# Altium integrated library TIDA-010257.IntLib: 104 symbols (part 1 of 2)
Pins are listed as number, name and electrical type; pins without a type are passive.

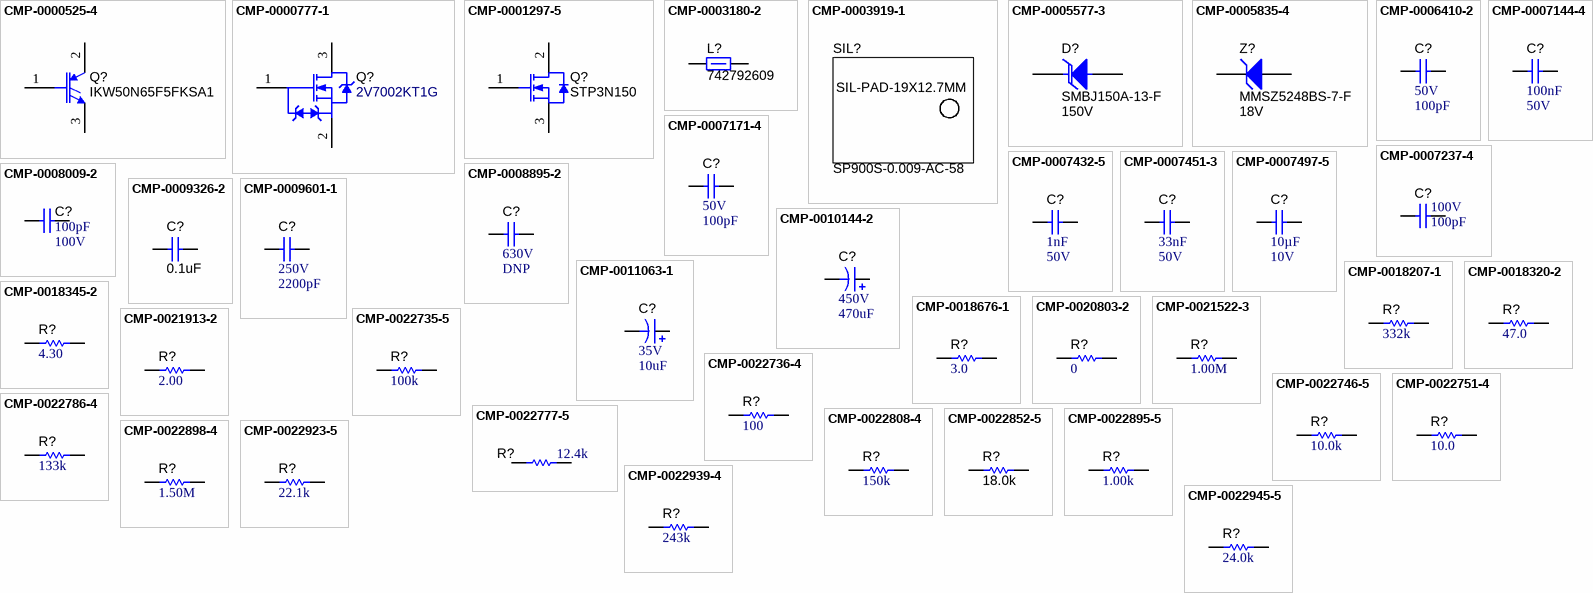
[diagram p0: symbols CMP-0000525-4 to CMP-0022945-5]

## CMP-0000525-4
designator Q?, comment IKW50N65F5FKSA1
Transistor, IGBT, 650 V, 50 A, TO-247; Manufacturer: Infineon Technologies; TaMin_C: -40°C; PNP: 0; AEC Qualified: N; TaMax_C: 175°C; SizeAreaWB_mm2: 123.2; Vceo_V: 650V; Vcesat1_V: 1.6V; Value1: 50 A; Value: 650 V; AEC Category: Q101; SizeArea_mm2: 78; SizeX_mm: 15.6; SizeY_mm: 5; SizeZ_mm: 25; IcRated_A: 50A
footprint TO-247 (Standard TO-247)
footprint TO-247_Horizontal_Down (TH, 3-Leads, Body 16.13x 21.1mm, Pitch 5.461mm)
pins: 1 G, 2 C, 3 E

## CMP-0000777-1
designator Q?, comment 2V7002KT1G
MOSFET, N-CH, 60 V, 0.32 A, AEC-Q101, SOT-23; Alternate Manufacturer: None; Manufacturer: ON Semiconductor; SizeZ_mm: 1.1; ChType: N; Value2: 0.7 nC; Value1: 2; VdsMax_V: 60V; SizeX_mm: 2.5; SizeY_mm: 3; Vgs_V: 20V; AEC Qualified: Y; Value: 60V; SizeArea_mm2: 7.5; AEC Category: Q101; IdsMax_A: 320mA; SizeAreaWB_mm2: 14; U/M: EA; QgTyp_nC: 0.7
footprint SOT-23 (SOT23, 3-Leads, Body 2.9x1.3mm, Pitch 0.95mm, Lead Span 2.5mm, IPC Medium Density)
footprint SOT-23L (SOT23, 3-Leads, Body 2.9x1.3mm, Pitch 0.95mm, Lead Span 2.5mm, IPC High Density)
footprint SOT-23M (SOT23, 3-Leads, Body 2.9x1.3mm, Pitch 0.95mm, Lead Span 2.5mm, IPC Low Density)
pins: 1 G, 2 S, 3 D

## CMP-0001297-5
designator Q?, comment STP3N150
MOSFET, N-CH, 1500 V, 2.5 A, TO-220AB; Alternate Manufacturer: None; Manufacturer: STMicroelectronics; SizeX_mm: 10.2; Vgs_V: 30V; AEC Category: Q101; ChMode: Enhancement; SizeArea_mm2: 45.9; SizeAreaWB_mm2: 79.3; VdsMax_V: 1.5kV; Value: 1500V; SizeY_mm: 4.5; Value2: 29.3 nC; IdsMax_A: 2.5A; U/M: EA; SizeZ_mm: 19.4; QgTyp_nC: 29.3; ChType: N
footprint TO-220AB (Copied from Altium's version of TO3B)
footprint TO-220AB_HORIZONTAL (For SolarMagic, with tab facing heatsink, away from PCB)
footprint TO-220AB_HORIZONTAL_SMT (For SolarMagic, with tab facing heatsink, away from PCB)
footprint TO-220AB_100mil (High Voltage staggered pins)
footprint TO-220AB_Horizontal_100mil (High Voltage staggered pins)
footprint TO-220AB_Horizontal_100mil_Standoff2300 (TH, 3-Leads, Body 10.67x9.4mm)
footprint TO-220AB_HORIZONTAL_TABUP_100mil
pins: 1 G, 2 D, 3 S
1 alternate drawing of the same symbol

## CMP-0003180-2
designator L?, comment 742792609
Ferrite Bead, 30 ohm @ 100 MHz, 3 A, 0603; Manufacturer: Wurth Elektronik; Ztyp@1GHz_Ohm: 40.472; ZTyp@100MHz_Ohm: 30; SizeAreaWB_mm2: 4.68; DCR_ohm: 40m; Value1: 0.04 ohm; Value: 30 ohm; Imax_A: 3A; SizeZ_mm: 1; SizeX_mm: 1.6; SizeY_mm: 0.8; SizeArea_mm2: 1.28
footprint 0603 (0603 from SM-752 data)
footprint 0603_HV (Ernesto recommended land pattern.  26 mil between pads.)
footprint 0603L (0603 from SM-752 data)
footprint 0603S
footprint 0603M (0603 from SM-752 data)
pins: 1, 2

## CMP-0003919-1
designator SIL?, comment SP900S-0.009-AC-58
Silcon Thermal Pad; Manufacturer: Bergquist Company
footprint SIL-PAD_19x12.7mm (Sil-Pad)

## CMP-0005577-3
designator D?, comment SMBJ150A-13-F  value 150V
Diode, TVS, Uni, 150 V, 243 Vc, SMB; Manufacturer: Diodes Inc.; Vbr_Max: 192.5V; Ipp: 2.5A; AEC Category: Q101; SizeArea_mm2: 21.336; Value1: 600W; SizeAreaWB_mm2: 44.156; Vc: 243V; SizeZ_mm: 2.6; SizeX_mm: 5.6; SizeY_mm: 3.81; Vbr_Min: 167V
footprint SMB (Molded Diode, 2-Leads, Body 5.4x3.6mm, IPC Medium Density, based on OnSemi component dimensions)
pins: 1 K, 2 A

## CMP-0005835-4
designator Z?, comment MMSZ5248BS-7-F  value 18V
Diode, Zener, 18 V, 200 mW, SOD-323; Manufacturer: Diodes Inc.; Value1: 0.2W; SizeArea_mm2: 3.645; AEC Category: Q101; Power_W: 200mW; SizeAreaWB_mm2: 8.695; SizeY_mm: 1.35; RJA_CperW: 350; SizeZ_mm: 1; SizeX_mm: 2.7
footprint SOD-323 (NXP recommended land pattern)
pins: 1 K, 2 A

## CMP-0006410-2
designator C?, comment VDC_V: 50V  ValueDisplayed: 100pF  (hidden comment: GRM1555C1H101JA01D)
CAP, CERM, 100 pF, 50 V, +/- 5%, C0G/NP0, 0402; Manufacturer: MuRata; TaMin_C: -55°C; Polarized: N; SizeAreaWB_mm2: 3; Value1: Unknown; U/M: EA; Value: 100pF; TaMax_C: 125°C; SizeZ_mm: 0.6; SizeX_mm: 1; SizeY_mm: 0.5; Cap_Case: 0402; CompType: Capacitor; AEC Category: Q200
footprint 0402 (0402 from SM-752 data)
footprint 0402S (Based on C0402S footprint from PADS legacy)
footprint 0402L (0402 from SM-752 data)
footprint 0402M (0402 from SM-752 data)
pins: 1, 2

## CMP-0007144-4
designator C?, comment Cap_F: 100nF  VDC_V: 50V  (hidden comment: GCM188R71H104KA57D)
CAP, CERM, 0.1 uF, 50 V, +/- 10%, X7R, 0603; Manufacturer: MuRata; TaMin_C: -55°C; ESR_ohm: 20m; Polarized: N; SizeAreaWB_mm2: 4.68; Value1: 0.02 ohm; U/M: EA; Value: 0.1uF; TaMax_C: 125°C; SizeZ_mm: 1; SizeX_mm: 1.6; SizeY_mm: 0.8; Cap_Case: 0603; SizeArea_mm2: 1.28; CompType: Capacitor; IRMS_A: 1.84A; AEC Category: Q200
footprint 0603 (0603 from SM-752 data)
footprint 0603_HV (Ernesto recommended land pattern.  26 mil between pads.)
footprint 0603L (0603 from SM-752 data)
footprint 0603S
footprint 0603M (0603 from SM-752 data)
pins: 1, 2

## CMP-0007171-4
designator C?, comment VDC_V: 50V  ValueDisplayed: 100pF  (hidden comment: GRM1885C1H101JA01D)
CAP, CERM, 100 pF, 50 V, +/- 5%, C0G/NP0, 0603; Manufacturer: MuRata; TaMin_C: -55°C; Polarized: N; SizeAreaWB_mm2: 4.68; Value1: Unknown; U/M: EA; Value: 100pF; TaMax_C: 125°C; SizeZ_mm: 1; SizeX_mm: 1.6; SizeY_mm: 0.8; Cap_Case: 0603; SizeArea_mm2: 1.28; CompType: Capacitor; AEC Category: Q200
footprint 0603 (0603 from SM-752 data)
footprint 0603_HV (Ernesto recommended land pattern.  26 mil between pads.)
footprint 0603L (0603 from SM-752 data)
footprint 0603S
footprint 0603M (0603 from SM-752 data)
pins: 1, 2

## CMP-0007237-4
designator C?, comment VDC_V: 100V  ValueDisplayed: 100pF  (hidden comment: GRM1885C2A101JA01D)
CAP, CERM, 100 pF, 100 V, +/- 5%, C0G/NP0, 0603; Manufacturer: MuRata; TaMin_C: -55°C; Polarized: N; SizeAreaWB_mm2: 4.68; Value1: Unknown; U/M: EA; Value: 100pF; TaMax_C: 125°C; SizeZ_mm: 1; SizeX_mm: 1.6; SizeY_mm: 0.8; Cap_Case: 0603; SizeArea_mm2: 1.28; CompType: Capacitor; AEC Category: Q200
footprint 0603 (0603 from SM-752 data)
footprint 0603_HV (Ernesto recommended land pattern.  26 mil between pads.)
footprint 0603L (0603 from SM-752 data)
footprint 0603S
footprint 0603M (0603 from SM-752 data)
pins: 1, 2

## CMP-0007432-5
designator C?, comment Cap_F: 1nF  VDC_V: 50V  (hidden comment: GRM188R71H102KA01D)
CAP, CERM, 1000 pF, 50 V, +/- 10%, X7R, 0603; Manufacturer: MuRata; TaMin_C: -55°C; Polarized: N; SizeAreaWB_mm2: 4.68; Value1: Unknown; U/M: EA; Value: 1000pF; TaMax_C: 125°C; SizeZ_mm: 1; SizeX_mm: 1.6; SizeY_mm: 0.8; Cap_Case: 0603; SizeArea_mm2: 1.28; CompType: Capacitor; AEC Category: Q200
footprint 0603 (0603 from SM-752 data)
footprint 0603_HV (Ernesto recommended land pattern.  26 mil between pads.)
footprint 0603L (0603 from SM-752 data)
footprint 0603S
footprint 0603M (0603 from SM-752 data)
pins: 1, 2

## CMP-0007451-3
designator C?, comment Cap_F: 33nF  VDC_V: 50V  (hidden comment: GRM188R71H333KA61D)
CAP, CERM, 0.033 uF, 50 V, +/- 10%, X7R, 0603; Manufacturer: MuRata; TaMin_C: -55°C; Polarized: N; SizeAreaWB_mm2: 4.68; Value1: Unknown; U/M: EA; TaMax_C: 125°C; SizeZ_mm: 1; SizeX_mm: 1.6; SizeY_mm: 0.8; Cap_Case: 0603; SizeArea_mm2: 1.28; CompType: Capacitor; AEC Category: Q200
footprint 0603 (0603 from SM-752 data)
footprint 0603_HV (Ernesto recommended land pattern.  26 mil between pads.)
footprint 0603L (0603 from SM-752 data)
footprint 0603S
footprint 0603M (0603 from SM-752 data)
pins: 1, 2

## CMP-0007497-5
designator C?, comment Cap_F: 10µF  VDC_V: 10V  (hidden comment: GRM188Z71A106MA73D)
CAP, CERM, 10 uF, 10 V, +/- 20%, X7R, 0603; Manufacturer: MuRata; TaMin_C: -55°C; Polarized: N; SizeAreaWB_mm2: 4.68; Value1: Unknown; U/M: EA; Value: 10uF; TaMax_C: 125°C; SizeZ_mm: 1; SizeX_mm: 1.6; SizeY_mm: 0.8; Cap_Case: 0603; SizeArea_mm2: 1.28; CompType: Capacitor; AEC Category: Q200
footprint 0603 (0603 from SM-752 data)
footprint 0603_HV (Ernesto recommended land pattern.  26 mil between pads.)
footprint 0603L (0603 from SM-752 data)
footprint 0603S
footprint 0603M (0603 from SM-752 data)
pins: 1, 2

## CMP-0008009-2
designator C?, comment VDC_V: 100V  ValueDisplayed: 100pF  (hidden comment: GCM2165C2A101JA16D)
CAP, CERM, 100 pF, 100 V, +/- 5%, C0G/NP0, AEC-Q200 Grade 1, 0805; Manufacturer: MuRata; TaMin_C: -55°C; Polarized: N; SizeAreaWB_mm2: 6.75; Value1: Unknown; U/M: EA; Value: 100pF; TaMax_C: 105°C; SizeZ_mm: 1.45; SizeX_mm: 2; SizeY_mm: 1.25; Cap_Case: 0805; SizeArea_mm2: 2.5; CompType: Capacitor; AEC Qualified: Y; AEC Grade: 1; AEC Category: Q200
footprint 0805_HV (0805 with 30mil clearance between pads)
footprint 0805M (0805 from SM-752 data)
footprint 0805 (0805 from SM-752 data)
footprint 0805L (0805 from SM-752 data)
footprint 0805_HV1 (Custom footprint based on analyzing multiple manufacturer recommendations)
pins: 1, 2

## CMP-0008895-2
designator C?, comment VDC_V: 630V  (hidden comment: DNP)
Manufacturer: MuRata; Manufacturer Part Number: GRM31A7U2J471JW31D; TaMin_C: -55°C; Polarized: N; TempCo: U2J; SizeAreaWB_mm2: 10.92; Value1: Unknown; U/M: EA; TaMax_C: 125°C; Tolerance_%: 5%; SizeZ_mm: 1.35; SizeX_mm: 3.2; SizeY_mm: 1.6; Cap_Case: 1206; SizeArea_mm2: 5.12; CompType: Capacitor; AEC Category: Q200
footprint 1206 (1206 from SM-752 data)
footprint 1206L (1206 from SM-752 data)
footprint 1206M (1206 from SM-752 data)
pins: 1, 2

## CMP-0009326-2
designator C?, comment ValueDisplayed: 0.1uF  (hidden comment: C1812W104KDRACTU)
CAP, CERM, 0.1 uF, 1000 V, +/- 10%, X7R, 1812; Manufacturer: Kemet; Polarized: N; CompType: Capacitor; Value: 0.1uF; U/M: EA; Cap_F: 100nF; Value1: Unknown; VDC_V: 1kV; Value2: 1000V; TaMin_C: -55°C; TaMax_C: 125°C; Cap_Case: 1812; AEC Category: Q200; SizeArea_mm2: 14.4; SizeAreaWB_mm2: 23.1; SizeX_mm: 4.5; SizeY_mm: 3.2; SizeZ_mm: 2.54
footprint 1812_254 (SMD, 2-Leads, Body 4.8x3.4mm)
pins: 1, 2

## CMP-0009601-1
designator C?, comment VDC_V: 250V  ValueDisplayed: 2200pF  (hidden comment: DE1E3KX222MA4BL01)
CAP, CERM, 2200 pF, 250 V, +/- 20%, E, Cap, 7x12x9 mm; Manufacturer: MuRata; TaMin_C: -25°C; Polarized: N; SizeAreaWB_mm2: 121.5; Value1: Unknown; U/M: EA; Value: 2200pF; TaMax_C: 85°C; SizeZ_mm: 12.5; SizeX_mm: 11.5; SizeY_mm: 7; Cap_Case: CAPRD1000W60D900H1200; SizeArea_mm2: 80.5; CompType: Capacitor; Cap_F: 2.2nF; AEC Category: Q200
footprint CAPRD1000W60D900H1200 (Disk, Radial Capacitor)
pins: 1, 2

## CMP-0010144-2
designator C?, comment VDC_V: 450V  ValueDisplayed: 470uF  (hidden comment: MAL215757471E3)
CAP, AL, 470 uF, 450 V, +/- 20%, 0.42 ohm, TH; Manufacturer: Vishay-Bccomponents; Manufacturer: Vishay/Bccomponents; TaMin_C: -25°C; ESR_ohm: 0.42; Polarized: Y; SizeAreaWB_mm2: 1369; U/M: EA; Value: 470uF; TaMax_C: 85°C; SizeZ_mm: 52; SizeX_mm: 35; Cap_Case: 35x50mm; SizeArea_mm2: 1225; CompType: Capacitor; AEC Qualified: N; Cap_F: 470µF; IRMS_A: 2.6A; AEC Category: Q200
footprint 157PUM-SI_3500x5000 (TH, 2-Leads, Dia 35mm, Pin Spacing 10mm)
pins: 1 +, 2 -

## CMP-0011063-1
designator C?, comment VDC_V: 35V  ValueDisplayed: 10uF  (hidden comment: EMZA350ADA100ME61G)
CAP, AL, 10 uF, 35 V, +/- 20%, 0.7 ohm, SMD; Manufacturer: Chemi-Con; TaMin_C: -55°C; ESR_ohm: 0.7; Polarized: Y; SizeAreaWB_mm2: 53.29; Value1: 0.7 ohm; U/M: EA; Value: 10uF; TaMax_C: 105°C; SizeZ_mm: 5.8; SizeX_mm: 5.3; Cap_Case: E61; SizeArea_mm2: 28.09; CompType: Capacitor; Cap_F: 10µF; IRMS_A: 160mA; AEC Category: Q200
footprint CAPSMT_62_E61 (5 x 5.8mm:  Chemi-Con E61)
pins: 1 +, 2 -

## CMP-0018207-1
designator R?, comment ValueDisplayed: 332k  (hidden comment: RC1206FR-07332KL)
RES, 332 k, 1%, 0.25 W, 1206; Manufacturer: Yageo America; Power_W: 250mW; TempCo: 100 ppm/C; U/M: EA; Value: 332k; EIA_Code: E96; SizeX_mm: 3.2; SizeY_mm: 1.6; SizeZ_mm: 1.35; Value2: 0.25W; SizeArea_mm2: 5.12; CompType: Resistor; VDC_V: 200V; AEC Category: Q200
footprint 1206 (1206 from SM-752 data)
footprint 1206L (1206 from SM-752 data)
footprint 1206M (1206 from SM-752 data)
pins: 1, 2

## CMP-0018320-2
designator R?, comment ValueDisplayed: 47.0  (hidden comment: RC1206FR-0747RL)
RES, 47.0, 1%, 0.25 W, 1206; Manufacturer: Yageo America; Power_W: 250mW; TempCo: 100 ppm/C; Value_Code: 47R0; U/M: EA; Value: 47.0; Res_ohm: 47; SizeX_mm: 3.2; SizeY_mm: 1.6; SizeZ_mm: 1.35; Value2: 0.25W; SizeArea_mm2: 5.12; CompType: Resistor; VDC_V: 200V; AEC Category: Q200
footprint 1206 (1206 from SM-752 data)
footprint 1206L (1206 from SM-752 data)
footprint 1206M (1206 from SM-752 data)
pins: 1, 2

## CMP-0018345-2
designator R?, comment ValueDisplayed: 4.30  (hidden comment: RC1206FR-074R3L)
RES, 4.30, 1%, 0.25 W, 1206; Manufacturer: Yageo America; Power_W: 250mW; TempCo: 200 ppm/C; Value_Code: 4R30; U/M: EA; Value: 4.30; Res_ohm: 4.3; SizeX_mm: 3.2; SizeY_mm: 1.6; SizeZ_mm: 1.35; Value2: 0.25W; SizeArea_mm2: 5.12; CompType: Resistor; VDC_V: 200V; AEC Category: Q200
footprint 1206 (1206 from SM-752 data)
footprint 1206L (1206 from SM-752 data)
footprint 1206M (1206 from SM-752 data)
pins: 1, 2

## CMP-0018676-1
designator R?, comment ValueDisplayed: 3.0  (hidden comment: CRCW12063R00JNEA)
RES, 3.0, 5%, 0.25 W, 1206; Manufacturer: Vishay-Dale; Manufacturer: Vishay/Dale; Power_W: 250mW; TempCo: 200 ppm/C; Value_Code: 3R00; U/M: EA; Value: 3.0; EIA_Code: E24; Res_ohm: 3; SizeX_mm: 3.2; SizeY_mm: 1.6; SizeZ_mm: 1.35; Value2: 0.25W; SizeArea_mm2: 5.12; CompType: Resistor; VDC_V: 200V; AEC Category: Q200
footprint 1206 (1206 from SM-752 data)
footprint 1206L (1206 from SM-752 data)
footprint 1206M (1206 from SM-752 data)
pins: 1, 2

## CMP-0020803-2
designator R?, comment ValueDisplayed: 0  (hidden comment: RC0805JR-070RL)
RES, 0, 5%, 0.125 W, 0805; Manufacturer: Yageo America; Power_W: 125mW; TempCo: 200 ppm/C; Value_Code: 0000; U/M: EA; Value: 0; EIA_Code: E24; SizeX_mm: 2; SizeY_mm: 1.25; SizeZ_mm: 1.45; Value2: 0.125W; SizeArea_mm2: 2.5; CompType: Resistor; VDC_V: 150V; AEC Category: Q200
footprint 0805_HV (0805 with 30mil clearance between pads)
footprint 0805M (0805 from SM-752 data)
footprint 0805 (0805 from SM-752 data)
footprint 0805L (0805 from SM-752 data)
footprint 0805_HV1 (Custom footprint based on analyzing multiple manufacturer recommendations)
pins: 1, 2

## CMP-0021522-3
designator R?, comment ValueDisplayed: 1.00M  (hidden comment: ERJ-6ENF1004V)
RES, 1.00 M, 1%, 0.125 W, AEC-Q200 Grade 0, 0805; Manufacturer: Panasonic; Power_W: 125mW; TempCo: 100 ppm/C; Value_Code: 1M00; Value: 1.00Meg; EIA_Code: E96; Res_ohm: 1M; SizeX_mm: 2; SizeY_mm: 1.25; SizeZ_mm: 1.45; Value2: 0.125W; SizeArea_mm2: 2.5; CompType: Resistor; AEC Qualified: Y; AEC Category: Q200; AEC Grade: 0; SizeAreaWB_mm2: 6.75
footprint 0805_HV (0805 with 30mil clearance between pads)
footprint 0805_HV1 (Custom footprint based on analyzing multiple manufacturer recommendations)
footprint 0805 (0805 from SM-752 data)
footprint 0805M (0805 from SM-752 data)
footprint 0805L (0805 from SM-752 data)
pins: 1, 2

## CMP-0021913-2
designator R?, comment ValueDisplayed: 2.00  (hidden comment: RC0805FR-072RL)
RES, 2.00, 1%, 0.125 W, 0805; Manufacturer: Yageo America; Power_W: 125mW; TempCo: 200 ppm/C; Value_Code: 2R00; U/M: EA; Value: 2.00; EIA_Code: E96; Res_ohm: 2; SizeY_mm: 1.25; SizeZ_mm: 1.45; Value2: 0.125W; SizeArea_mm2: 2.5; CompType: Resistor; VDC_V: 150V; AEC Category: Q200
footprint 0805_HV (0805 with 30mil clearance between pads)
footprint 0805M (0805 from SM-752 data)
footprint 0805 (0805 from SM-752 data)
footprint 0805L (0805 from SM-752 data)
footprint 0805_HV1 (Custom footprint based on analyzing multiple manufacturer recommendations)
pins: 1, 2

## CMP-0022735-5
designator R?, comment ValueDisplayed: 100k  (hidden comment: RC0603FR-07100KL)
RES, 100 k, 1%, 0.1 W, 0603; Manufacturer: Yageo; Power_W: 100mW; TempCo: 100 ppm/C; Value: 100k; EIA_Code: E96; SizeX_mm: 1.6; SizeY_mm: 0.8; SizeZ_mm: 1; Value2: 0.1W; SizeArea_mm2: 1.28; CompType: Resistor; AEC Qualified: N; VDC_V: 75V; AEC Category: Q200; SizeAreaWB_mm2: 4.68
footprint 0603 (0603 from SM-752 data)
footprint 0603_HV (Ernesto recommended land pattern.  26 mil between pads.)
footprint 0603L (0603 from SM-752 data)
footprint 0603S
footprint 0603M (0603 from SM-752 data)
pins: 1, 2

## CMP-0022736-4
designator R?, comment ValueDisplayed: 100  (hidden comment: RC0603FR-07100RL)
RES, 100, 1%, 0.1 W, 0603; Manufacturer: Yageo; Power_W: 100mW; TempCo: 100 ppm/C; Value_Code: 100R; Value: 100; EIA_Code: E96; SizeX_mm: 1.6; SizeY_mm: 0.8; SizeZ_mm: 1; Value2: 0.1W; SizeArea_mm2: 1.28; CompType: Resistor; AEC Qualified: N; VDC_V: 75V; AEC Category: Q200; SizeAreaWB_mm2: 4.68
footprint 0603 (0603 from SM-752 data)
footprint 0603_HV (Ernesto recommended land pattern.  26 mil between pads.)
footprint 0603L (0603 from SM-752 data)
footprint 0603S
footprint 0603M (0603 from SM-752 data)
pins: 1, 2

## CMP-0022746-5
designator R?, comment ValueDisplayed: 10.0k  (hidden comment: RC0603FR-0710KL)
RES, 10.0 k, 1%, 0.1 W, 0603; Manufacturer: Yageo; Power_W: 100mW; TempCo: 100 ppm/C; Value_Code: 10k0; Value: 10.0k; EIA_Code: E96; Res_ohm: 10k; SizeX_mm: 1.6; SizeY_mm: 0.8; SizeZ_mm: 1; Value2: 0.1W; SizeArea_mm2: 1.28; CompType: Resistor; AEC Qualified: N; VDC_V: 75V; AEC Category: Q200; SizeAreaWB_mm2: 4.68
footprint 0603 (0603 from SM-752 data)
footprint 0603_HV (Ernesto recommended land pattern.  26 mil between pads.)
footprint 0603L (0603 from SM-752 data)
footprint 0603S
footprint 0603M (0603 from SM-752 data)
pins: 1, 2

## CMP-0022751-4
designator R?, comment ValueDisplayed: 10.0  (hidden comment: RC0603FR-0710RL)
RES, 10.0, 1%, 0.1 W, 0603; Manufacturer: Yageo; Power_W: 100mW; TempCo: 100 ppm/C; Value_Code: 10R0; Value: 10.0; EIA_Code: E96; Res_ohm: 10; SizeX_mm: 1.6; SizeY_mm: 0.8; SizeZ_mm: 1; Value2: 0.1W; SizeArea_mm2: 1.28; CompType: Resistor; AEC Qualified: N; VDC_V: 75V; AEC Category: Q200; SizeAreaWB_mm2: 4.68
footprint 0603 (0603 from SM-752 data)
footprint 0603_HV (Ernesto recommended land pattern.  26 mil between pads.)
footprint 0603L (0603 from SM-752 data)
footprint 0603S
footprint 0603M (0603 from SM-752 data)
pins: 1, 2

## CMP-0022777-5
designator R?, comment ValueDisplayed: 12.4k  (hidden comment: RC0603FR-0712K4L)
RES, 12.4 k, 1%, 0.1 W, 0603; Manufacturer: Yageo; Power_W: 100mW; TempCo: 100 ppm/C; Value_Code: 12k4; Value: 12.4k; EIA_Code: E96; SizeX_mm: 1.6; SizeY_mm: 0.8; SizeZ_mm: 1; Value2: 0.1W; SizeArea_mm2: 1.28; CompType: Resistor; AEC Qualified: N; VDC_V: 75V; AEC Category: Q200; SizeAreaWB_mm2: 4.68
footprint 0603 (0603 from SM-752 data)
footprint 0603_HV (Ernesto recommended land pattern.  26 mil between pads.)
footprint 0603L (0603 from SM-752 data)
footprint 0603S
footprint 0603M (0603 from SM-752 data)
pins: 1, 2

## CMP-0022786-4
designator R?, comment ValueDisplayed: 133k  (hidden comment: RC0603FR-07133KL)
RES, 133 k, 1%, 0.1 W, 0603; Manufacturer: Yageo; Power_W: 100mW; TempCo: 100 ppm/C; Value: 133k; EIA_Code: E96; SizeX_mm: 1.6; SizeY_mm: 0.8; SizeZ_mm: 1; Value2: 0.1W; SizeArea_mm2: 1.28; CompType: Resistor; AEC Qualified: N; VDC_V: 75V; AEC Category: Q200; SizeAreaWB_mm2: 4.68
footprint 0603 (0603 from SM-752 data)
footprint 0603_HV (Ernesto recommended land pattern.  26 mil between pads.)
footprint 0603L (0603 from SM-752 data)
footprint 0603S
footprint 0603M (0603 from SM-752 data)
pins: 1, 2

## CMP-0022808-4
designator R?, comment ValueDisplayed: 150k  (hidden comment: RC0603FR-07150KL)
RES, 150 k, 1%, 0.1 W, 0603; Manufacturer: Yageo; Power_W: 100mW; TempCo: 100 ppm/C; Value: 150k; EIA_Code: E96; SizeX_mm: 1.6; SizeY_mm: 0.8; SizeZ_mm: 1; Value2: 0.1W; SizeArea_mm2: 1.28; CompType: Resistor; AEC Qualified: N; VDC_V: 75V; AEC Category: Q200; SizeAreaWB_mm2: 4.68
footprint 0603 (0603 from SM-752 data)
footprint 0603_HV (Ernesto recommended land pattern.  26 mil between pads.)
footprint 0603L (0603 from SM-752 data)
footprint 0603S
footprint 0603M (0603 from SM-752 data)
pins: 1, 2

## CMP-0022852-5
designator R?, comment ValueDisplayed: 18.0k  (hidden comment: RC0603FR-0718KL)
RES, 18.0 k, 1%, 0.1 W, 0603; Manufacturer: Yageo; Power_W: 100mW; TempCo: 100 ppm/C; Value_Code: 18k0; Value: 18.0k; Res_ohm: 18k; SizeX_mm: 1.6; SizeY_mm: 0.8; SizeZ_mm: 1; Value2: 0.1W; SizeArea_mm2: 1.28; CompType: Resistor; AEC Qualified: N; VDC_V: 75V; AEC Category: Q200; SizeAreaWB_mm2: 4.68
footprint 0603 (0603 from SM-752 data)
footprint 0603_HV (Ernesto recommended land pattern.  26 mil between pads.)
footprint 0603L (0603 from SM-752 data)
footprint 0603S
footprint 0603M (0603 from SM-752 data)
pins: 1, 2

## CMP-0022895-5
designator R?, comment ValueDisplayed: 1.00k  (hidden comment: RC0603FR-071KL)
RES, 1.00 k, 1%, 0.1 W, 0603; Manufacturer: Yageo; Power_W: 100mW; TempCo: 100 ppm/C; Value_Code: 1k00; Value: 1.00k; EIA_Code: E96; Res_ohm: 1k; SizeX_mm: 1.6; SizeY_mm: 0.8; SizeZ_mm: 1; Value2: 0.1W; SizeArea_mm2: 1.28; CompType: Resistor; AEC Qualified: N; VDC_V: 75V; AEC Category: Q200; SizeAreaWB_mm2: 4.68
footprint 0603 (0603 from SM-752 data)
footprint 0603_HV (Ernesto recommended land pattern.  26 mil between pads.)
footprint 0603L (0603 from SM-752 data)
footprint 0603S
footprint 0603M (0603 from SM-752 data)
pins: 1, 2

## CMP-0022898-4
designator R?, comment ValueDisplayed: 1.50M  (hidden comment: RC0603FR-071M5L)
RES, 1.50 M, 1%, 0.1 W, 0603; Manufacturer: Yageo; Power_W: 100mW; TempCo: 100 ppm/C; Value_Code: 1M50; Value: 1.50Meg; EIA_Code: E96; Res_ohm: 1.5M; SizeX_mm: 1.6; SizeY_mm: 0.8; SizeZ_mm: 1; Value2: 0.1W; SizeArea_mm2: 1.28; CompType: Resistor; AEC Qualified: N; VDC_V: 75V; AEC Category: Q200; SizeAreaWB_mm2: 4.68
footprint 0603 (0603 from SM-752 data)
footprint 0603_HV (Ernesto recommended land pattern.  26 mil between pads.)
footprint 0603L (0603 from SM-752 data)
footprint 0603S
footprint 0603M (0603 from SM-752 data)
pins: 1, 2

## CMP-0022923-5
designator R?, comment ValueDisplayed: 22.1k  (hidden comment: RC0603FR-0722K1L)
RES, 22.1 k, 1%, 0.1 W, 0603; Manufacturer: Yageo; Power_W: 100mW; TempCo: 100 ppm/C; Value_Code: 22k1; Value: 22.1k; EIA_Code: E96; SizeX_mm: 1.6; SizeY_mm: 0.8; SizeZ_mm: 1; Value2: 0.1W; SizeArea_mm2: 1.28; CompType: Resistor; AEC Qualified: N; VDC_V: 75V; AEC Category: Q200; SizeAreaWB_mm2: 4.68
footprint 0603 (0603 from SM-752 data)
footprint 0603_HV (Ernesto recommended land pattern.  26 mil between pads.)
footprint 0603L (0603 from SM-752 data)
footprint 0603S
footprint 0603M (0603 from SM-752 data)
pins: 1, 2

## CMP-0022939-4
designator R?, comment ValueDisplayed: 243k  (hidden comment: RC0603FR-07243KL)
RES, 243 k, 1%, 0.1 W, 0603; Manufacturer: Yageo; Power_W: 100mW; TempCo: 100 ppm/C; Value: 243k; EIA_Code: E96; SizeX_mm: 1.6; SizeY_mm: 0.8; SizeZ_mm: 1; Value2: 0.1W; SizeArea_mm2: 1.28; CompType: Resistor; AEC Qualified: N; VDC_V: 75V; AEC Category: Q200; SizeAreaWB_mm2: 4.68
footprint 0603 (0603 from SM-752 data)
footprint 0603_HV (Ernesto recommended land pattern.  26 mil between pads.)
footprint 0603L (0603 from SM-752 data)
footprint 0603S
footprint 0603M (0603 from SM-752 data)
pins: 1, 2

## CMP-0022945-5
designator R?, comment ValueDisplayed: 24.0k  (hidden comment: RC0603FR-0724KL)
RES, 24.0 k, 1%, 0.1 W, 0603; Manufacturer: Yageo; Power_W: 100mW; TempCo: 100 ppm/C; Value_Code: 24k0; Value: 24.0k; Res_ohm: 24k; SizeX_mm: 1.6; SizeY_mm: 0.8; SizeZ_mm: 1; Value2: 0.1W; SizeArea_mm2: 1.28; CompType: Resistor; AEC Qualified: N; VDC_V: 75V; AEC Category: Q200; SizeAreaWB_mm2: 4.68
footprint 0603 (0603 from SM-752 data)
footprint 0603_HV (Ernesto recommended land pattern.  26 mil between pads.)
footprint 0603L (0603 from SM-752 data)
footprint 0603S
footprint 0603M (0603 from SM-752 data)
pins: 1, 2

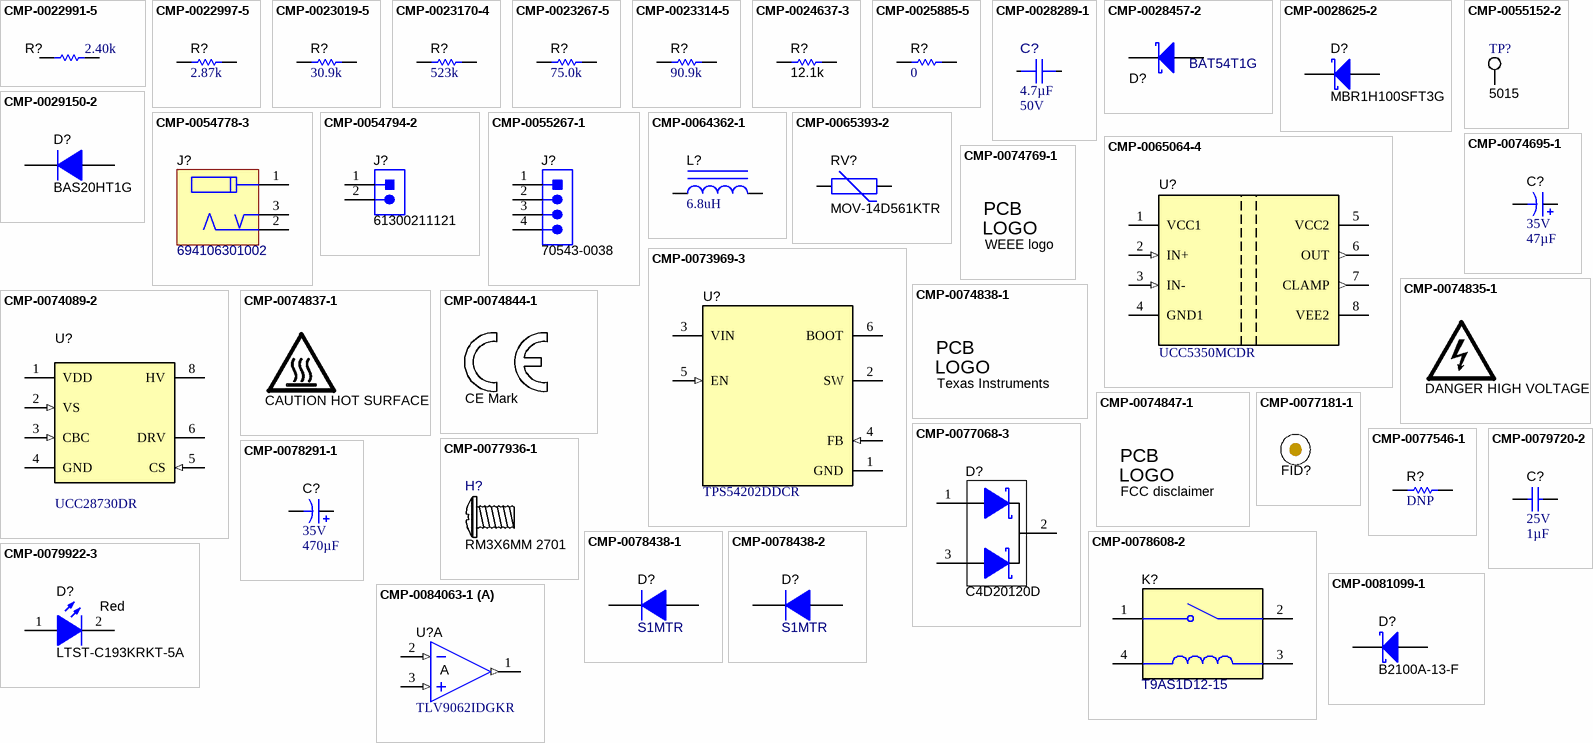
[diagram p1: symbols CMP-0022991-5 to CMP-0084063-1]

## CMP-0022991-5
designator R?, comment ValueDisplayed: 2.40k  (hidden comment: RC0603FR-072K4L)
RES, 2.40 k, 1%, 0.1 W, 0603; Manufacturer: Yageo; Power_W: 100mW; TempCo: 100 ppm/C; Value_Code: 2k40; Value: 2.40k; Res_ohm: 2.4k; SizeX_mm: 1.6; SizeY_mm: 0.8; SizeZ_mm: 1; Value2: 0.1W; SizeArea_mm2: 1.28; CompType: Resistor; AEC Qualified: N; VDC_V: 75V; AEC Category: Q200; SizeAreaWB_mm2: 4.68
footprint 0603 (0603 from SM-752 data)
footprint 0603_HV (Ernesto recommended land pattern.  26 mil between pads.)
footprint 0603L (0603 from SM-752 data)
footprint 0603S
footprint 0603M (0603 from SM-752 data)
pins: 1, 2

## CMP-0022997-5
designator R?, comment ValueDisplayed: 2.87k  (hidden comment: RC0603FR-072K87L)
RES, 2.87 k, 1%, 0.1 W, 0603; Manufacturer: Yageo; Power_W: 100mW; TempCo: 100 ppm/C; Value_Code: 2k87; Value: 2.87k; EIA_Code: E96; SizeX_mm: 1.6; SizeY_mm: 0.8; SizeZ_mm: 1; Value2: 0.1W; SizeArea_mm2: 1.28; CompType: Resistor; AEC Qualified: N; VDC_V: 75V; AEC Category: Q200; SizeAreaWB_mm2: 4.68
footprint 0603 (0603 from SM-752 data)
footprint 0603_HV (Ernesto recommended land pattern.  26 mil between pads.)
footprint 0603L (0603 from SM-752 data)
footprint 0603S
footprint 0603M (0603 from SM-752 data)
pins: 1, 2

## CMP-0023019-5
designator R?, comment ValueDisplayed: 30.9k  (hidden comment: RC0603FR-0730K9L)
RES, 30.9 k, 1%, 0.1 W, 0603; Manufacturer: Yageo; Power_W: 100mW; TempCo: 100 ppm/C; Value_Code: 30k9; Value: 30.9k; EIA_Code: E96; SizeX_mm: 1.6; SizeY_mm: 0.8; SizeZ_mm: 1; Value2: 0.1W; SizeArea_mm2: 1.28; CompType: Resistor; AEC Qualified: N; VDC_V: 75V; AEC Category: Q200; SizeAreaWB_mm2: 4.68
footprint 0603 (0603 from SM-752 data)
footprint 0603_HV (Ernesto recommended land pattern.  26 mil between pads.)
footprint 0603L (0603 from SM-752 data)
footprint 0603S
footprint 0603M (0603 from SM-752 data)
pins: 1, 2

## CMP-0023170-4
designator R?, comment ValueDisplayed: 523k  (hidden comment: RC0603FR-07523KL)
RES, 523 k, 1%, 0.1 W, 0603; Manufacturer: Yageo; Power_W: 100mW; TempCo: 100 ppm/C; Value: 523k; EIA_Code: E96; SizeX_mm: 1.6; SizeY_mm: 0.8; SizeZ_mm: 1; Value2: 0.1W; SizeArea_mm2: 1.28; CompType: Resistor; AEC Qualified: N; VDC_V: 75V; AEC Category: Q200; SizeAreaWB_mm2: 4.68
footprint 0603 (0603 from SM-752 data)
footprint 0603_HV (Ernesto recommended land pattern.  26 mil between pads.)
footprint 0603L (0603 from SM-752 data)
footprint 0603S
footprint 0603M (0603 from SM-752 data)
pins: 1, 2

## CMP-0023267-5
designator R?, comment ValueDisplayed: 75.0k  (hidden comment: RC0603FR-0775KL)
RES, 75.0 k, 1%, 0.1 W, 0603; Manufacturer: Yageo; Power_W: 100mW; TempCo: 100 ppm/C; Value_Code: 75k0; Value: 75.0k; EIA_Code: E96; Res_ohm: 75k; SizeX_mm: 1.6; SizeY_mm: 0.8; SizeZ_mm: 1; Value2: 0.1W; SizeArea_mm2: 1.28; CompType: Resistor; AEC Qualified: N; VDC_V: 75V; AEC Category: Q200; SizeAreaWB_mm2: 4.68
footprint 0603 (0603 from SM-752 data)
footprint 0603_HV (Ernesto recommended land pattern.  26 mil between pads.)
footprint 0603L (0603 from SM-752 data)
footprint 0603S
footprint 0603M (0603 from SM-752 data)
pins: 1, 2

## CMP-0023314-5
designator R?, comment ValueDisplayed: 90.9k  (hidden comment: RC0603FR-0790K9L)
RES, 90.9 k, 1%, 0.1 W, 0603; Manufacturer: Yageo; Power_W: 100mW; TempCo: 100 ppm/C; Value_Code: 90k9; Value: 90.9k; EIA_Code: E96; SizeX_mm: 1.6; SizeY_mm: 0.8; SizeZ_mm: 1; Value2: 0.1W; SizeArea_mm2: 1.28; CompType: Resistor; AEC Qualified: N; VDC_V: 75V; AEC Category: Q200; SizeAreaWB_mm2: 4.68
footprint 0603 (0603 from SM-752 data)
footprint 0603_HV (Ernesto recommended land pattern.  26 mil between pads.)
footprint 0603L (0603 from SM-752 data)
footprint 0603S
footprint 0603M (0603 from SM-752 data)
pins: 1, 2

## CMP-0024637-3
designator R?, comment ValueDisplayed: 12.1k  (hidden comment: RT0603DRE0712K1L)
RES, 12.1 k, 0.5%, 0.1 W, 0603; Manufacturer: Yageo America; Power_W: 100mW; TempCo: 50 ppm/C; Value_Code: 12k1; U/M: EA; Value: 12.1k; EIA_Code: E192; SizeX_mm: 1.6; SizeY_mm: 0.8; SizeZ_mm: 1; Value2: 0.1W; SizeArea_mm2: 1.28; CompType: Resistor; VDC_V: 75V; AEC Category: Q200
footprint 0603 (0603 from SM-752 data)
footprint 0603_HV (Ernesto recommended land pattern.  26 mil between pads.)
footprint 0603L (0603 from SM-752 data)
footprint 0603S
footprint 0603M (0603 from SM-752 data)
pins: 1, 2

## CMP-0025885-5
designator R?, comment ValueDisplayed: 0  (hidden comment: RC0603JR-070RL)
RES, 0, 5%, 0.1 W, 0603; Manufacturer: Yageo; Power_W: 100mW; TempCo: 200 ppm/C; Value_Code: 0000; Value: 0; EIA_Code: E24; SizeX_mm: 1.6; SizeZ_mm: 1; Value2: 0.1W; SizeArea_mm2: 1.28; CompType: Resistor; AEC Qualified: N; VDC_V: 75V; AEC Category: Q200; SizeY_mm: 0.8; SizeAreaWB_mm2: 4.68
footprint 0603 (0603 from SM-752 data)
footprint 0603_HV (Ernesto recommended land pattern.  26 mil between pads.)
footprint 0603L (0603 from SM-752 data)
footprint 0603S
footprint 0603M (0603 from SM-752 data)
pins: 1, 2

## CMP-0028289-1
designator C?, comment Cap_F: 4.7µF  VDC_V: 50V  (hidden comment: GRM21BZ71H475KE15L)
Chip Multilayer Ceramic Capacitors for General Purpose, 0805, 4.7uF, X7R, 15%, 10%, 50V; Manufacturer: Murata; AEC Qualified: No; SizeZ_mm: 1.45mm; Value: 4.7µF
footprint FP-GRM21BZ71H475KE15L_0805-MFG
footprint FP-GRM21BZ71H475KE15L_0805-IPC_C
footprint FP-GRM21BZ71H475KE15L_0805-IPC_B
footprint FP-GRM21BZ71H475KE15L_0805-IPC_A
pins: 1, 2

## CMP-0028457-2
designator D?, comment BAT54T1G
Diode, Schottky, 30 V, 0.2 A, SOD-123; Manufacturer: ON Semiconductor; SizeArea_mm2: 6.545; Io_A: 200mA; SizeX_mm: 3.85; Value1: 0.2A; SizeY_mm: 1.7; AEC Category: Q101; Vf_V: 800mV; TJmax_C: 125°C; Green_Lifecycle: Not Set; RJC_CperW: 174; Value: 30V; Value2: 0.8V; SizeAreaWB_mm2: 13.095; Green_REACh: Incomplete; SizeZ_mm: 1.35
footprint SOD-123 (On Semi recommended land pattern)
pins: 1 K, 2 A

## CMP-0028625-2
designator D?, comment MBR1H100SFT3G
Diode, Schottky, 100 V, 1 A, SOD-123FL; Manufacturer: ON Semiconductor; Value2: 0.76V; Vr_V: 100V; RJC_CperW: 85; SizeZ_mm: 0.98; Io_A: 1A; Green_Lifecycle: Active; SizeX_mm: 3.6; AEC Category: Q101; Vf_V: 760mV; SizeAreaWB_mm2: 12.19; SizeArea_mm2: 5.94; Green_REACh: Passed; Value: 100V; TJmax_C: 175°C; SizeY_mm: 1.65
footprint SOD-123FL (Copied from SOD-123)
pins: 1 K, 2 A

## CMP-0029150-2
designator D?, comment BAS20HT1G
Diode, Switching, 200 V, 0.2 A, AEC-Q101, SOD-323; Manufacturer: ON Semiconductor; Value2: 1.25V; Value1: 0.2A; SizeZ_mm: 1; Green_REACh: Incomplete; SizeArea_mm2: 3.645; Vr_V: 200V; SizeX_mm: 2.7; TJmax_C: 150°C; Io_A: 200mA; Value: 200V; Green_Lifecycle: Not Set; SizeAreaWB_mm2: 8.695; AEC Qualified: Y; AEC Category: Q101; SizeY_mm: 1.35
footprint SOD-323 (NXP recommended land pattern)
pins: 1 K, 2 A

## CMP-0054778-3
designator J?, comment 694106301002
WR-DC DC Power Jack, R/A, TH; Manufacturer: Wurth Elektronik; Gender: Male
footprint Wurth_694106301002 (WR-DC DC Power Jack, R/A, TH)
pins: 1, 2, 3

## CMP-0054794-2
designator J?, comment 61300211121
Header, 2.54 mm, 2x1, Gold, TH; Manufacturer: Wurth Elektronik; Manufacturer: Wurth Electronics; Shrouded: N; Gender: Male; Green_REACh: Passed; Pitch_mm: 2.54; Green_Lifecycle: Active; Row_Count: 1; Cert_UL: Y
footprint WURTH_61300211121 (Header, 2.54mm, 2x1, TH)
pins: 1, 2
1 alternate drawing of the same symbol

## CMP-0055152-2
designator TP?, comment 5015
Test Point, Miniature, SMT; Manufacturer: Keystone Electronics; CT: TRUE; Green_Lifecycle: Active; Green_REACh: Passed; CNHeader: FALSE
footprint Testpoint_Keystone_Miniature (Miniature SMT test point)
pins: 1

## CMP-0055267-1
designator J?, comment 70543-0038
Header(shrouded), 2.54mm, 4x1, Tin, TH; Manufacturer: Molex; CNHeader: FALSE; Shrouded: Y; Gender: Male; Row_Count: 1; Pitch_mm: 2.54
footprint Molex_70543-0038 (Header(shrouded), 2.54mm, 4x1, TH)
pins: 1, 2, 3, 4

## CMP-0064362-1
designator L?, comment ValueDisplayed: 6.8uH  (hidden comment: 78438335068)
Inductor, Shielded, Powdered Iron, 6.8 uH, 1.1 A, 0.287 ohm, AEC-Q200 Grade 1, SMD; Manufacturer: Wurth Elektronik; Isat: 2.4A @ 20% inductance drop; Irms: 1.1A @ 40C rise; SizeAreaWB_mm2: 16; DCR_ohm: 0.287; Value: 6.8uH; Imax_A: 1.1A; SizeZ_mm: 1.5; SizeX_mm: 3; SizeArea_mm2: 9; Ind_H: 6.8µH; AEC Qualified: Y; AEC Grade: 1; AEC Category: Q200
footprint WE-MAIA_3015 (SMD, 2-Leads, Body 3x3mm)
pins: 1, 2

## CMP-0065064-4
designator U?, comment UCC5350MCDR
4.3-A, 3-kVRMS Isolated Single-Channel Gate Drivers, D0008B (SOIC-8); Manufacturer: Texas Instruments; SizeX_mm: 6.0; SizeY_mm: 4.9; CompType: IC; SizeZ_mm: 1.75; SizeArea_mm2: 29.4; SizeAreaWB_mm2: 55.2; U/M: EA
footprint D0008B_HV (SOIC, 8-Leads, Body 4.9x3.9mm, Pitch 1.27mm, HV / Isolation option)
footprint D0008B_L (SOIC, 8-Leads, Body 4.9x3.9mm, Pitch 1.27mm, IPC High Density)
footprint D0008B_M (SOIC, 8-Leads, Body 4.9x3.9mm, Pitch 1.27mm, IPC Low Density)
footprint D0008B_N (SOIC, 8-Leads, Body 4.9x3.9mm, Pitch 1.27mm, IPC Medium Density)
pins: 1 VCC1 (power), 2 IN+ (in), 3 IN- (in), 4 GND1 (power), 5 VCC2 (power), 6 OUT (out), 7 CLAMP (out), 8 VEE2 (power)

## CMP-0065393-2
designator RV?, comment MOV-14D561KTR
VARISTOR 560V 4.5KA, TH; Manufacturer: Bourns; SizeAreaWB_mm2: 148.0; SizeZ_mm: 22.0; SizeX_mm: 16.5; SizeY_mm: 6.0; SizeArea_mm2: 99.0
footprint Bourns_MOV-14D561K (TH, 2-Leads, Dia 16.5mm)
pins: 1, 2

## CMP-0073969-3
designator U?, comment TPS54202DDCR
4.5V to 28V Input, 2A Output, EMI Friendly Synchronous Step-Down Converter, DDC0006A (SOT-23-THIN-6); Alternate PartNumber: TPS54202DDCT; Manufacturer: Texas Instruments; SizeZ_mm: 0.87; SizeX_mm: 1.65; SizeY_mm: 2.95; SizeArea_mm2: 4.8675; CompType: IC; SizeAreaWB_mm2: 10.4675; AEC Category: Q200; AEC Qualified: N; Rating: Catalog
footprint DDC0006A_N
footprint DDC0006A_M
footprint DDC0006A_L
pins: 1 GND (power), 2 SW (power), 3 VIN (power), 4 FB (in), 5 EN (in), 6 BOOT (power)

## CMP-0074089-2
designator U?, comment UCC28730DR
Zero Standby PSR Flyback Controller with CVCC and Wake-Up Monitoring, D0007A (SOIC-7); Alternate Manufacturer: Texas Instruments; SizeAreaWB_mm2: 55.2; U/M: EA; SizeZ_mm: 1.75; SizeX_mm: 6.0; SizeY_mm: 4.9; SizeArea_mm2: 29.4; CompType: IC; AEC Category: Q200; AEC Qualified: N
footprint D0007A_N (SOIC, 7-Leads, Body 4.9x3.9mm, Pitch 1.27mm, IPC Medium Density)
footprint D0007A_L (SOIC, 7-Leads, Body 4.9x3.9mm, Pitch 1.27mm, IPC High Density)
footprint D0007A_M (SOIC, 7-Leads, Body 4.9x3.9mm, Pitch 1.27mm, IPC Low Density)
pins: 1 VDD (power), 2 VS (in), 3 CBC (in), 4 GND (power), 5 CS (in), 6 DRV (power), 8 HV (power)
1 alternate drawing of the same symbol

## CMP-0074695-1
designator C?, comment VDC_V: 35V  ValueDisplayed: 47µF  (hidden comment: EKZN350ELL470ME11D)
CAP, AL, 47 µF, 35 V, +/- 20%, 0.38 ohm, TH; Manufacturer: Chemi-Con; TaMin_C: -40°C; ESR_ohm: 0.38; Polarized: Y; SizeAreaWB_mm2: 49.0; U/M: EA; Value: 47uF; TaMax_C: 105°C; SizeZ_mm: 12.5; SizeX_mm: 5.0; Cap_Case: 5x11; SizeArea_mm2: 25.0; CompType: Capacitor; AEC Qualified: N; IRMS_A: 450mA; AEC Category: Q200
footprint Chemi-Con_500x1100 (TH, 2-Leads, Dia 5mm, Lead Sapcing 2mm)
pins: 1 +, 2 -

## CMP-0074769-1
designator Logo?, comment WEEE logo  (no BOM)
footprint WEEE_Minimum (WEEElie bin)

## CMP-0074835-1
designator LOGO?, comment DANGER HIGH VOLTAGE  (no BOM)
IEC 61010-1 High Voltage Warning; SymbolCreator: a0412235; Lib Reference: IEC_HighVoltage
footprint IEC_HighVoltage_Large
footprint IEC_HighVoltage_Small
footprint IEC_HighVoltage_Medium

## CMP-0074837-1
designator LOGO?, comment CAUTION HOT SURFACE  (no BOM)
IEC 61010-1 Hot Surface Warning; SymbolCreator: a0412235; Lib Reference: IEC_HotSurface
footprint IEC_HotSurface_Large
footprint IEC_HotSurface_Small
footprint IEC_HotSurface_Medium

## CMP-0074838-1
designator Logo?, comment Texas Instruments  (no BOM)
Texas Instrument Corporate Signature; SymbolCreator: a0412235; Lib Reference: TI_Logo; Library Reference: Logo
footprint TI_Horizontal_Overlay_Medium
footprint TI_Horizontal_Overlay_Small
footprint TI_Stacked_SolderMask_Small
footprint TI_Stacked_SolderMask_Small_Vertical
footprint TI_Symbol_Overlay_Medium
footprint TI_Symbol_Overlay_Small
footprint TI_Symbol_SolderMask_Medium
footprint TI_Symbol_SolderMask_Small
footprint TI_Horizontal_SolderMask_Medium
footprint TI_Horizontal_SolderMask_Small
footprint TI_Stacked_Overlay_Medium
footprint TI_Stacked_Overlay_Medium_Vertical
footprint TI_Stacked_Overlay_Small
footprint TI_Stacked_Overlay_Small_Vertical
footprint TI_Stacked_SolderMask_Medium
footprint TI_Stacked_SolderMask_Medium_Vertical

## CMP-0074844-1
designator Logo?, comment CE Mark  (no BOM)
SymbolCreator: a0412235
footprint CE_Mark_5mm (Minimum text height for CE Mark)
footprint CE_Mark_10mm (Double the minimum text height for CE Mark)

## CMP-0074847-1
designator Logo?, comment FCC disclaimer  (no BOM)
FCC_disclaimer; Library Reference: Logo
footprint FCC_disclaimer
footprint FCC_disclaimer_stacked

## CMP-0077068-3
designator D?, comment C4D20120D
Diode, Schottky, 1200 V, 34 A, TH; Manufacturer: Cree; SizeZ_mm: 25.0; Value: 1200V; SizeArea_mm2: 78.0; SizeX_mm: 15.6; Value2: 1.8V; SizeAreaWB_mm2: 123.2; Green_Lifecycle: Not Set; Value1: 34A; Green_REACh: Incomplete; TJmax_C: 175°C; AEC Qualified: N; SizeY_mm: 5.0; AEC Category: Q101; Vr_V: 1.2kV; RJC_CperW: 0.85
footprint TO-247 (Standard TO-247)
footprint TO-247_Horizontal_Down (TH, 3-Leads, Body 16.13x 21.1mm, Pitch 5.461mm)
pins: 1 A, 2 K, 3 A

## CMP-0077181-1
designator FID?, comment Fiducial  (value not drawn)
Fiducial mark.  There is nothing to buy or mount.
footprint Fiducial10-30
footprint Fiducial15-30
footprint Fiducial10-20
footprint Fiducial20-40
footprint Fiducial6.4-20

## CMP-0077546-1
designator R?, comment DNP
Power_W: 62.5mW; TempCo: 50 ppm/C; Value1: 1%; U/M: EA; EIA_Code: E96; SizeX_mm: 1.6; SizeY_mm: 0.8; SizeZ_mm: 1.0; Value2: 0.0625W; SizeArea_mm2: 1.28; CompType: Resistor; AEC Qualified: N; VDC_V: 50V; AEC Category: Q200
footprint 0603 (0603 from SM-752 data)
footprint 0603_HV (Ernesto recommended land pattern.  26 mil between pads.)
footprint 0603L (0603 from SM-752 data)
footprint 0603S
footprint 0603M (0603 from SM-752 data)
pins: 1, 2

## CMP-0077936-1
designator H?, comment RM3X6MM 2701  (mechanical)
MACHINE SCREW PAN PHILLIPS M3; Manufacturer: APM HEXSEAL; CompType: Standoff

## CMP-0078291-1
designator C?, comment VDC_V: 35V  ValueDisplayed: 470µF  (hidden comment: 35ZLG470MEFC10X20)
CAP, AL, 470 µF, 35 V, +/- 20%, TH; Manufacturer: Rubycon; IRMS_A: 2.18A; SizeAreaWB_mm2: 144; SizeArea_mm2: 100; AEC Qualified: N; AEC Category: Q200; Value: 470uF; TaMax_C: 105°C; SizeZ_mm: 22; Polarized: Y; TaMin_C: -40°C; SizeY_mm: 10; U/M: EA; CompType: Capacitor; Cap_Case: 10x20mm
footprint ZLG_1000x2000 (TH, 2-Leads, Dia 10mm,  Lead Spacing 5mm)
pins: 1 +, 2 -

## CMP-0078438-1
designator D?, comment S1MTR
Diode, Standard Recovery Rectifier, 1000 V, 1 A, SMA; Manufacturer: SMC Diode Solutions; Manufacturer: SMC; SizeAreaWB_mm2: 37.3428; Vr_V: 1kV; SizeArea_mm2: 16.3228; AEC Qualified: N; TJmax_C: 175°C; AEC Category: Q101; Value: 1000V; SizeZ_mm: 2.87; Io_A: 1A; Vf_V: 1.1V; SizeY_mm: 2.92; SizeX_mm: 5.59
footprint SMA (Molded Diode, 2-Leads, Body 4.3x2.6mm, IPC Medium Density, based on OnSemi component dimensions and land pattern)
pins: 1 K, 2 A

## CMP-0078438-2
designator D?, comment S1MTR
Diode, Standard Recovery Rectifier, 1000 V, 1 A, SMA; Manufacturer: SMC Diode Solutions; Manufacturer: SMC; Vf_V: 1.1V; TJmax_C: 175°C; SizeZ_mm: 2.87; SizeY_mm: 2.92; AEC Qualified: N; Vr_V: 1kV; Value1: 1A; SizeAreaWB_mm2: 37.3428; SizeArea_mm2: 16.3228; Value: 1000V; AEC Category: Q101; SizeX_mm: 5.59
footprint SMA (Molded Diode, 2-Leads, Body 4.3x2.6mm, IPC Medium Density, based on OnSemi component dimensions and land pattern)
pins: 1 K, 2 A

## CMP-0078608-2
designator K?, comment T9AS1D12-15
Relay, SPST-NO (1 Form A), 30 A, 15 V, TH; Manufacturer: TE Connectivity; Contact Rating_A: 30A; Turn On Voltage (Max)_VDC: 11.25V; Coil Power_W: 1W; Coil Resistance_ohm: 225; SizeAreaWB_mm2: 1015.6293; Time Operate (s): 15ms; Coil Current_A: 66.7mA; SizeZ_mm: 20.4; SizeX_mm: 32.51; SizeY_mm: 27.43; SizeArea_mm2: 891.7493; Turn Off Voltage (Min)_VDC: 1.5V; Coil Type: Non Latching; Coil Voltage_VDC: 15V
footprint Relay_T9AS1D12 (TH, 4-Leads, Body 32.51x27.43mm)
pins: 1, 2, 3, 4

## CMP-0079720-2
designator C?, comment VDC_V: 25V  Cap_F: 1µF  (hidden comment: GRJ188R71E105KE11D)
CAP, CERM, 1 µF, 25 V,+/- 10%, X7R, 0603; Manufacturer: MuRata; AEC Category: Q200; TaMin_C: -55°C; Cap_Case: 0603; AEC Qualified: N; SizeAreaWB_mm2: 4.68; CompType: Capacitor; SizeArea_mm2: 1.28; Value: 1uF; SizeZ_mm: 1; SizeX_mm: 1.6; U/M: EA; MFG_Status: TI_Obsolete; SizeY_mm: 0.8; TaMax_C: 125°C
footprint 0603 (0603 from SM-752 data)
footprint 0603M (0603 from SM-752 data)
footprint 0603L (0603 from SM-752 data)
footprint 0603_HV (Ernesto recommended land pattern.  26 mil between pads.)
footprint 0603S
pins: 1, 2

## CMP-0079922-3
designator D?, comment LTST-C193KRKT-5A  value Red
LED, Red, SMD; Manufacturer: Lite-On; Manufacturer: Vishay Lite-On; SizeX_mm: 1.6; Value2: 2V; SizeY_mm: 0.8; Green_REACh: Incomplete; SizeAreaWB_mm2: 4.68; Green_Lifecycle: Not Set; Value1: W; Io_A: 5mA; Type: AlInGaP; SizeZ_mm: 0.45; Tjmax_C: 85°C; SizeArea_mm2: 1.28
footprint LTST-C193_Red (SMD, 2-Leads, Body1.6x0.8mm)
pins: 1 A, 2 K

## CMP-0081099-1
designator D?, comment B2100A-13-F
Diode, Schottky, 100 V, 2 A, SMA; Manufacturer: Diodes Inc.; Manufacturer: Diodes; SizeAreaWB_mm2: 37.3428; Vr_V: 100V; SizeArea_mm2: 16.3228; AEC Qualified: N; TJmax_C: 125°C; AEC Category: Q101; Value: 100V; SizeZ_mm: 2.87; Io_A: 2A; Vf_V: 7.9dV; SizeY_mm: 2.92; Value2: 0.79V; SizeX_mm: 5.59
footprint SMA (Molded Diode, 2-Leads, Body 4.3x2.6mm, IPC Medium Density, based on OnSemi component dimensions and land pattern)
pins: 1 K, 2 A

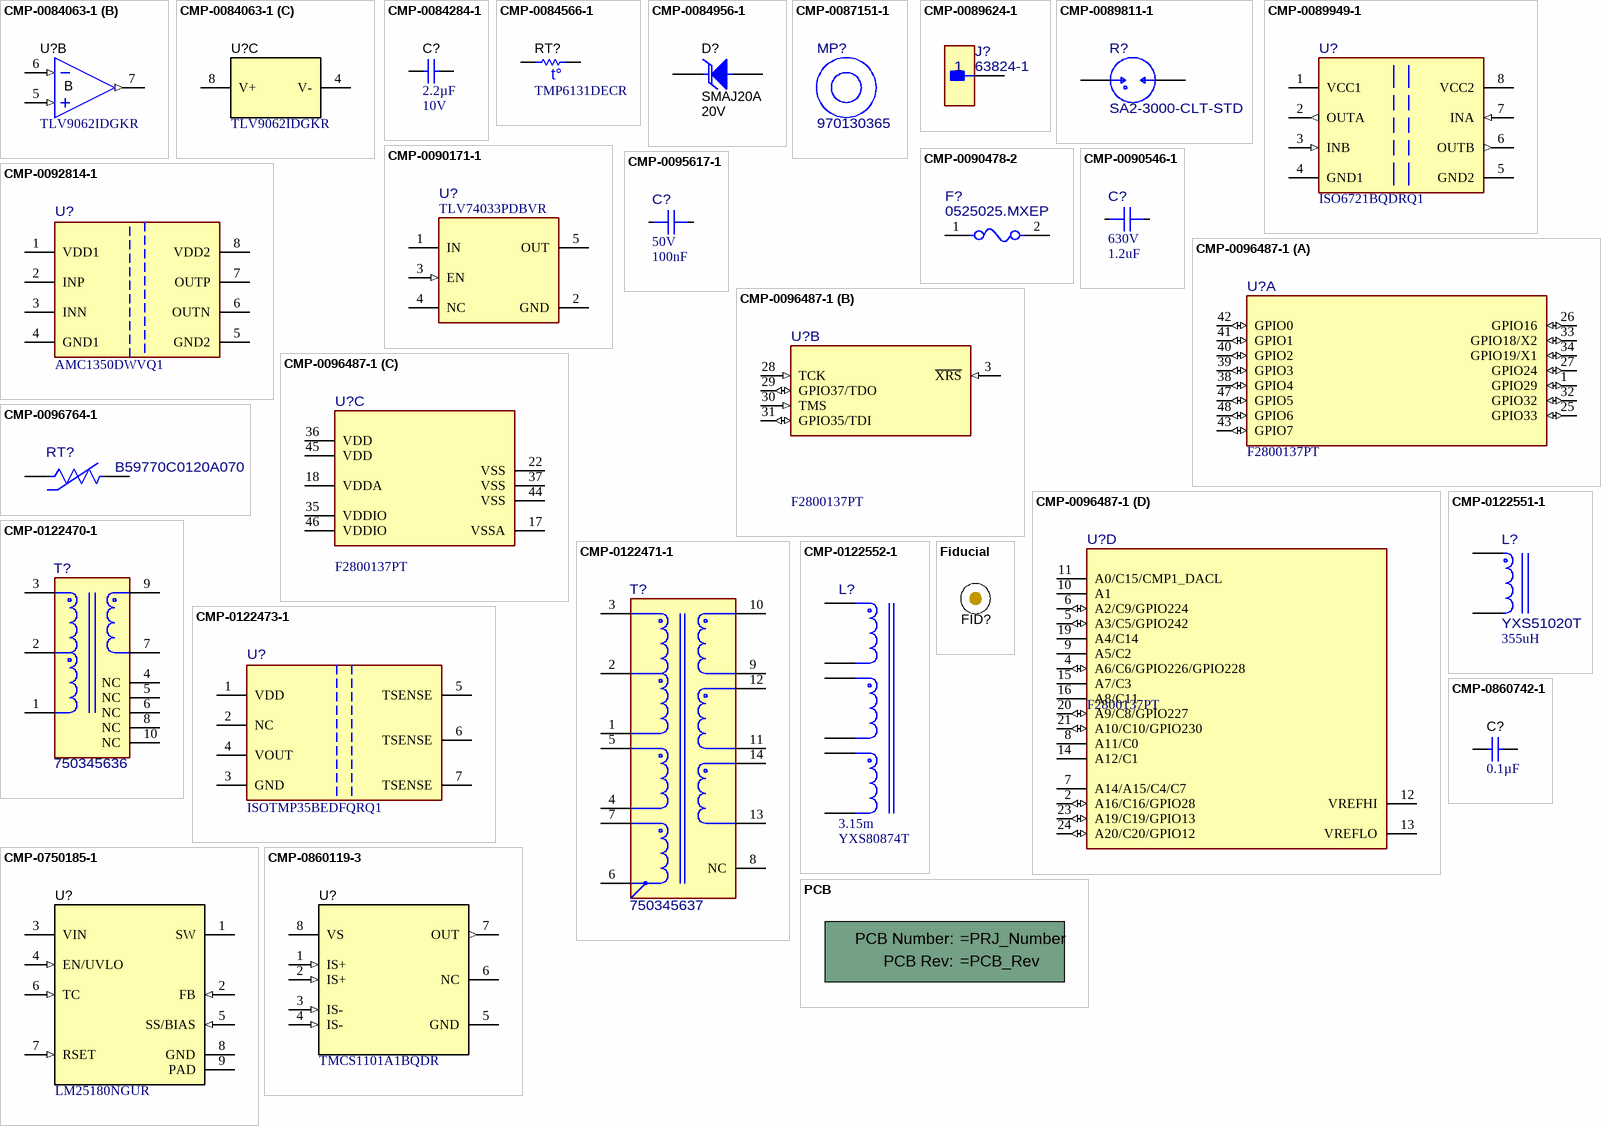
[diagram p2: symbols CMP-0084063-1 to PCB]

## CMP-0084063-1
designator U?, comment TLV9062IDGKR
10-MHz, Low-Noise, RRIO, CMOS Operational Amplifier for Cost-Sensitive Systems, DGK0008A (VSSOP-8); Manufacturer: Texas Instruments; Alternate PartNumber: TLV9062IDGKT; Rating: Catalog; SizeAreaWB_mm2: 23.6; SizeArea_mm2: 14.7; AEC Qualified: N; AEC Category: Q200; SizeZ_mm: 1.1; SizeY_mm: 3; CompType: IC; SizeX_mm: 4.9
footprint DGK0008A_N (TSOP, 8-Leads, Body 3x3mm, Pitch 0.65mm, IPC Medium Density)
footprint DGK0008A_M (TSOP, 8-Leads, Body 3x3mm, Pitch 0.65mm, IPC Low Density)
footprint DGK0008A_L (TSOP, 8-Leads, Body 3x3mm, Pitch 0.65mm, IPC High Density)
part A pins: 1 OUT (out), 2 IN- (in), 3 IN+ (in)
part B pins: 5 IN+ (in), 6 IN- (in), 7 OUT (out)
part C pins: 4 V- (power), 8 V+ (power)

## CMP-0084284-1
designator C?, comment Cap_F: 2.2µF  VDC_V: 10V  (hidden comment: GRM188R71A225KE15J)
CAP, CERM, 2.2 µF, 10 V,+/- 10%, X7R, AEC-Q200 Grade 1, 0603; Manufacturer: MuRata; SizeAreaWB_mm2: 4.68; Polarized: N; AEC Qualified: Y; SizeX_mm: 1.6; SizeZ_mm: 1; SizeY_mm: 0.8; U/M: EA; TaMin_C: -55°C; Value: 2.2uF; Cap_Case: 0603; AEC Category: Q200; TaMax_C: 125°C; CompType: Capacitor; SizeArea_mm2: 1.28
footprint 0603 (0603 from SM-752 data)
footprint 0603M (0603 from SM-752 data)
footprint 0603L (0603 from SM-752 data)
footprint 0603_HV (Ernesto recommended land pattern.  26 mil between pads.)
footprint 0603S
pins: 1, 2

## CMP-0084566-1
designator RT?, comment TMP6131DECR
Thermistor, DEC0002A (X1SON-2); Alternate Manufacturer: Texas Instruments; Alternate PartNumber: TMP6131DECT; CompType: IC; AEC Category: Q200; SizeX_mm: 1; AEC Qualified: N; SizeZ_mm: 0.5; SizeArea_mm2: 0.6; SizeAreaWB_mm2: 3.2
footprint DEC0002A (X1SON-2)
pins: 1, 2

## CMP-0084956-1
designator D?, comment SMAJ20A  value 20V
Diode, TVS, Uni, 20 V, 32.4 Vc, 400 W, 12.3 A, SMA; Manufacturer: Littelfuse; SizeZ_mm: 2.87; Value1: 32.4V; AEC Qualified: N; SizeX_mm: 5.59; Vbr_Max: 24.5V; Ipp: 12.3A; SizeY_mm: 2.92; Ppk: 400W; AEC Category: Q101; RJA_CperW: 120; Vbr_Min: 22.2V; SizeArea_mm2: 16.3228; SizeAreaWB_mm2: 37.3428
footprint SMA (Molded Diode, 2-Leads, Body 4.3x2.6mm, IPC Medium Density, based on OnSemi component dimensions and land pattern)
pins: 1 K, 2 A

## CMP-0087151-1
designator MP?, comment 970130365
Manufacturer: Wurth Electronics; Symbol Name: SYM-970130365
footprint FP-970130365_SPCAER_M3-MFG

## CMP-0089624-1
designator J?, comment 63824-1
Manufacturer: TE Connectivity; SizeZ_mm: 10.71mm; Conn Gender: Male; Conn Orientation: Straight; AEC Qualified: No; Import Ts: 1521847382; ContactFinish: Tin,Nickel; Current_A: 20A; Ciiva Ids: 766930
footprint FP-63824-1_CONN_7MM92_3MM11-MFG
pins: 1

## CMP-0089811-1
designator R?, comment SA2-3000-CLT-STD
Gas Discharge Tube 3000V 5000A (5kA) ±20% 2 Pole Through Hole; Manufacturer: Bourns; SizeZ_mm: 8.6mm; AEC Qualified: No
footprint FP-SA2-3000-CLT-STD_AXIAL-MFG
pins: 1, 2

## CMP-0089949-1
designator U?, comment ISO6721BQDRQ1
Low Speed, General Purpose, Robust EMC, Dual-Channel Digital Isolators; Manufacturer: Texas Instruments; TJmax_C: +150°C; TaMin_C: -40°C; SizeZ_mm: 1.75mm; Min Supply Voltage: 1.71V; Standoff Height: 0.11mm; AEC Qualified: Yes; TaMax_C: +125°C; AEC Grade: Grade 1; Max Supply Voltage: 5.5V; Interface: LVCMOS
footprint D0008A-MFG
footprint D0008A-IPC_C
footprint D0008A-IPC_B
footprint D0008A-IPC_A
pins: 1 VCC1 (power), 2 OUTA (out), 3 INB (in), 4 GND1 (power), 5 GND2 (power), 6 OUTB (out), 7 INA (in), 8 VCC2 (power)

## CMP-0090171-1
designator U?, comment TLV74033PDBVR
300-mA low-dropout (LDO) regulator with foldback current limit 5-SOT-23 -40 to 125; Manufacturer: Texas Instruments; SizeZ_mm: 1.45mm; Output Type: Fixed; Nominal Supply Current: 50uA; TJmax_C: +85°C; Max Supply Voltage: 5.5V; Standoff Height: 0mm; AEC Qualified: No; Accuracy Percentage: 1%; Output Voltage: 3.3V; Number Of Outputs: 1; Dropout Voltage: 460mV
footprint DBV0005A-MFG
footprint DBV0005A-IPC_C
footprint DBV0005A-IPC_B
footprint DBV0005A-IPC_A
pins: 1 IN (power), 2 GND (power), 3 EN (in), 4 NC, 5 OUT

## CMP-0090478-2
designator F?, comment 0525025.MXEP
Manufacturer: Littelfuse; SizeZ_mm: 7.285mm; Fuse Interrupt Dc Current: 10000A; AEC Qualified: Yes; Res_ohm: 0.0038Ω; Fuse I2T: 320A2Sec; Fuse Current: 25A; AEC Grade: Grade 1; Interrupt_DC: 10kA; VDC_V: 450V
footprint FP-0525025.MXEP_AXIAL-MFG
footprint FP-0525025.MXEP_VM-MFG
pins: 1, 2

## CMP-0090546-1
designator C?, comment VDC_V: 630V  ValueDisplayed: 1.2uF  (hidden comment: 890334027012CS)
1.2µF Film Capacitor 310V  Polypropylene (PP), Metallized Radial; Manufacturer: Wurth Electronics; AEC Qualified: No; Tolerance_%: 10%; SizeZ_mm: 22.5mm
footprint FP-890334027012CS_RADIAL-MFG
pins: 1, 2

## CMP-0092814-1
designator U?, comment AMC1350DWVQ1
Precision, ±5-V Input, Reinforced Isolated Amplifier; Manufacturer: Texas Instruments; Bandwidth: 275kHz; Input Bias Current: 0.0035uA; SizeZ_mm: 2.8mm; Output Current Per Channel: 14mA; TaMax_C: +125°C; Input Offset Voltage: 0.4mV; TaMin_C: -55°C; Standoff Height: 0.36mm; Min Supply Voltage: 3V; TJmax_C: +150°C; AEC Qualified: No; Max Supply Voltage: 5.5V; Number Of Channels: 1
footprint DWV0008A-MFG
footprint DWV0008A-IPC_C
footprint DWV0008A-IPC_B
footprint DWV0008A-IPC_A
pins: 1 VDD1 (power), 2 INP (hiz), 3 INN (hiz), 4 GND1 (power), 5 GND2 (power), 6 OUTN, 7 OUTP, 8 VDD2 (power)

## CMP-0095617-1
designator C?, comment VDC_V: 50V  Cap_F: 100nF  (hidden comment: GCM188R71H104KA57J)
0603 50 V 0.1 uF X7R ±10% Tolerance SMT Multilayer Ceramic Capacitor; Manufacturer: Murata; TempCo: 15%; SizeZ_mm: 0.9mm; AEC Qualified: No; ValueDisplayed: 0.1uF; Value: 100nF
footprint FP-GCM188R71H104KA57J_0603-MFG
footprint FP-GCM188R71H104KA57J_0603-IPC_C
footprint FP-GCM188R71H104KA57J_0603-IPC_B
footprint FP-GCM188R71H104KA57J_0603-IPC_A
pins: 1, 2

## CMP-0096487-1
designator U?, comment F2800137PT
Real-Time Microcontrollers; Manufacturer: Texas Instruments; Number Of Pwm Channels: 14; Number Of Spi Channels: 1; Memory Type: FLASH; Frequency_Fixed: 120MHz; TaMin_C: -40°C; Number Of I2C Channels: 2; AEC Qualified: No; TaMax_C: +125°C; Number Of Adc Channels: 17; Ram Size: 36KBytes; Min Supply Voltage: 2.8V; Number Of Timers/Counters: 4; Core Architecture: TMS320C28x; Data Bus Width: 32bits; Number Of Uart Channels: 3; SizeZ_mm: 1.6mm; Memory Size: 256KBytes; Standoff Height: 0.5mm; Max Supply Voltage: 3.63V; Number Of I/Os: 25; Interface: I2C,SPI,UART,CAN,SCI,SMBus
footprint PT0048A-MFG
footprint PT0048A-IPC_C
footprint PT0048A-IPC_B
footprint PT0048A-IPC_A
part A pins: 1 GPIO29 (io), 25 GPIO33 (io), 26 GPIO16 (io), 27 GPIO24 (io), 32 GPIO32 (io), 33 GPIO18/X2 (io), 34 GPIO19/X1 (io), 38 GPIO4 (io), 39 GPIO3 (io), 40 GPIO2 (io), 41 GPIO1 (io), 42 GPIO0 (io), 43 GPIO7 (io), 47 GPIO5 (io), 48 GPIO6 (io)
part B pins: 3 ~{XRS} (in), 28 TCK (in), 29 GPIO37/TDO (io), 30 TMS (in), 31 GPIO35/TDI (io)
part C pins: 17 VSSA (power), 18 VDDA (power), 22 VSS (power), 35 VDDIO (power), 36 VDD (power), 37 VSS (power), 44 VSS (power), 45 VDD (power), 46 VDDIO (power)
part D pins: 2 A16/C16/GPIO28 (io), 4 A6/C6/GPIO226/GPIO228 (io), 5 A3/C5/GPIO242 (io), 6 A2/C9/GPIO224 (io), 7 A14/A15/C4/C7, 8 A11/C0, 9 A5/C2, 10 A1, 11 A0/C15/CMP1_DACL, 12 VREFHI, 13 VREFLO, 14 A12/C1, 15 A7/C3, 16 A8/C11, 19 A4/C14, 20 A9/C8/GPIO227 (io), 21 A10/C10/GPIO230 (io), 23 A19/C19/GPIO13 (io), 24 A20/C20/GPIO12 (io)

## CMP-0096764-1
designator RT?, comment B59770C0120A070
PTC Thermistor 70 Ohms Disc, 13mm Dia x 7.5mm W; Manufacturer: TDK; Manufacturer: TDK EPCOS; AEC Qualified: No; Tolerance_%: 25%; Value: 70Ω; SizeZ_mm: 13.5mm; VDC_V: 370V
footprint FP-B59770C0120A070_RADIAL-MFG
pins: 1, 2

## CMP-0122470-1
designator T?, comment 750345636
TRANSFORMER; Manufacturer: Wurth Electornics; Ind_H: 12mH; Ns1toNp: 18.89:1; SizeZ_mm: 21mm; AEC Qualified: No; Frequency_Fixed: 100kHz; Voltage_Isolation_Vrms: 3.2kV
footprint FP-750345636_PTH10-MFG
pins: 1, 2, 3, 4 NC, 5 NC, 6 NC, 7, 8 NC, 9, 10 NC

## CMP-0122471-1
designator T?, comment 750345637
TRANSFORMER; Manufacturer: Wurth Electornics; Ind_H: 39µH; Ns1toNp: 1:1.06; SizeZ_mm: 16mm; AEC Qualified: No; Frequency_Fixed: 180kHz
footprint FP-750345637_PTH_XFRMR_21MM0_19MM0-MFG
pins: 1, 2, 3, 4, 5, 6, 7, 8 NC, 9, 10, 11, 12, 13, 14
